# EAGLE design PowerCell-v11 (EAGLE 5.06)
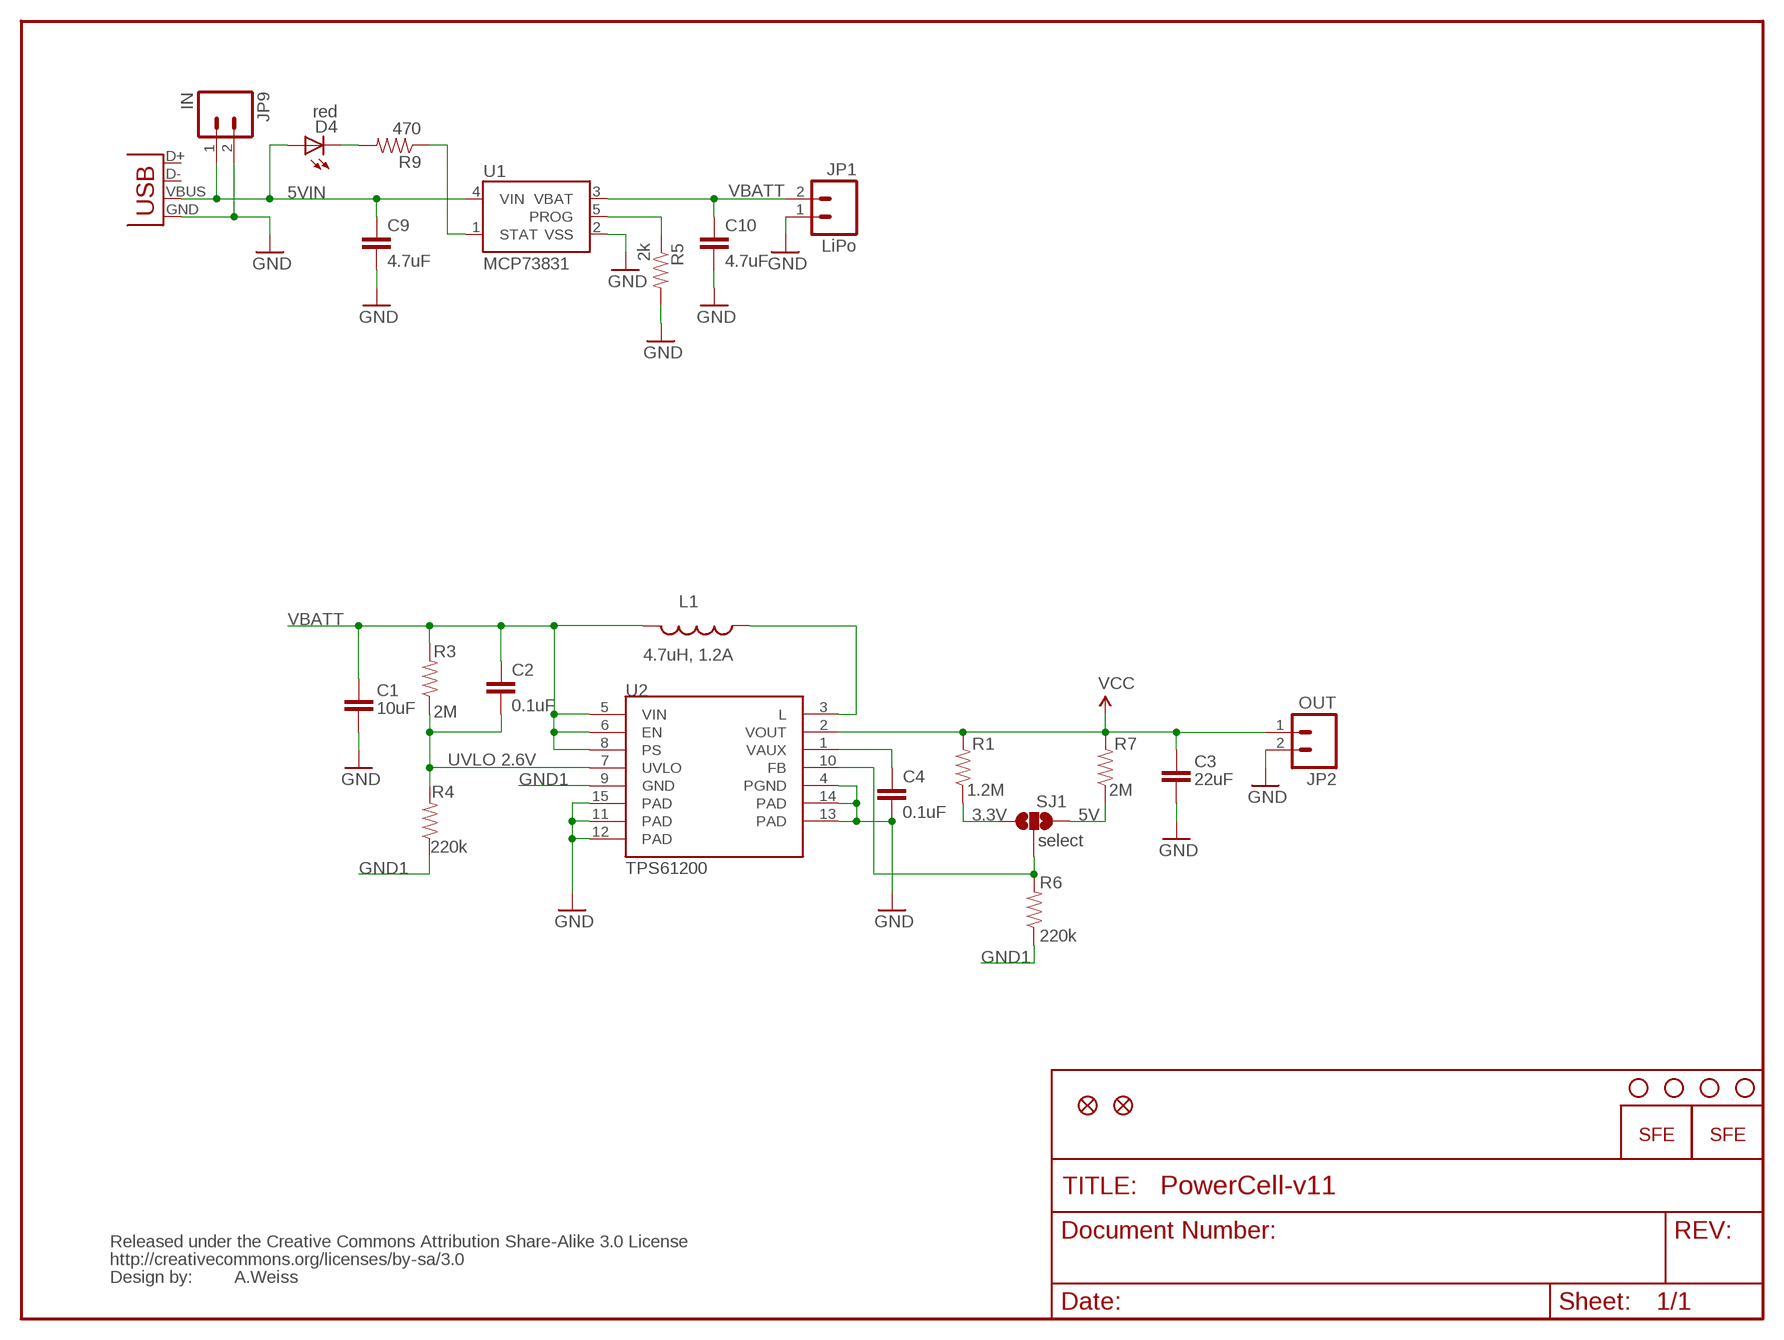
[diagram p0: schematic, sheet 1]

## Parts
C1  10uF  CAP1206  [1206]
C2  0.1uF  CAP0402-CAP  [0402-CAP]
C3  22uF  CAP0805  [0805]
C4  0.1uF  CAP0402-CAP  [0402-CAP]
C9  4.7uF  CAP0402-CAP  [0402-CAP]
C10  4.7uF  CAP0402-CAP  [0402-CAP]
D4  red  LED0603  [LED-0603]
JP1  LiPo  M02-JST-2MM-SMT  [JST-2-SMD]
JP2  OUT  M02PTH  [1X02]
JP3  LOGO-SFENEW  [SFE-NEW-WEBLOGO]
JP4  LOGO-SFESK  [SFE-LOGO-FLAME]
JP5  STAND-OFF  [STAND-OFF]
JP6  STAND-OFF  [STAND-OFF]
JP7  STAND-OFF  [STAND-OFF]
JP8  STAND-OFF  [STAND-OFF]
JP9  IN  M02PTH  [1X02]
JP10  FIDUCIAL1X2  [FIDUCIAL-1X2]
JP11  FIDUCIAL1X2  [FIDUCIAL-1X2]
L1  4.7uH, 1.2A  INDUCTOR.  [CDRH2D09]
R1  1.2M  RESISTOR0402-RES  [0402-RES]
R3  2M  RESISTOR0402-RES  [0402-RES]
R4  220k  RESISTOR0402-RES  [0402-RES]
R5  2k  RESISTOR0402-RES  [0402-RES]
R6  220k  RESISTOR0402-RES  [0402-RES]
R7  2M  RESISTOR0402-RES  [0402-RES]
R9  470  RESISTOR0402-RES  [0402-RES]
SJ1  select  SOLDERJUMPER_2WAYPASTE2&3  [SJ_3_PASTE2&3]
U1  MCP73831  [SOT23-5]
U2  TPS61200  [QFN-10_PAD]
U$1  CREATIVE_COMMONS  [CREATIVE_COMMONS]
X1  USB-MICROB  [USB-MICROB]

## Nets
3.3V: R1.1 SJ1.1
5V: R7.1 SJ1.3
5VIN: C9.1 D4.A JP9.1 U1.4(VIN) X1.VBUS
FB: R6.2 SJ1.2 U2.10(FB)
GND: C1.2 C3.2 C4.2 C9.2 C10.2 JP1.1 JP2.2 JP9.2 R5.2 U1.2(VSS) U2.4(PGND) U2.11(PAD) U2.12(PAD) U2.13(PAD) U2.14(PAD) U2.15(PAD) X1.GND
GND1: R4.1 R6.1 U2.9(GND)
N$1: C4.1 U2.1(VAUX)
N$2: L1.P$1 U2.3(L)
N$8: D4.C R9.2
N$11: R5.1 U1.5(PROG)
N$14: R9.1 U1.1(STAT)
UVLO: C2.2 R3.1 R4.2 U2.7(UVLO)
VBATT: C1.1 C2.1 C10.1 JP1.2 L1.P$2 R3.2 U1.3(VBAT) U2.5(VIN) U2.6(EN) U2.8(PS)
VCC: C3.1 JP2.1 R1.2 R7.2 U2.2(VOUT)
Unconnected: X1.D+ X1.D-

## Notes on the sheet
- UVLO 2.6V
- A.Weiss

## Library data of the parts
C1 C3 = CH_passive:CAP: Capacitor
C2 C4 C9 C10 = SparkFun:CAP: Capacitor
D4 = SparkFun:LED: LEDs
JP1 JP2 JP9 = SparkFun:M02: Header 2
JP3 JP4 = SparkFun:LOGO-SFE: Spark Fun Electronics PCB Logo
JP5-JP8 = SparkFun:STAND-OFF: Stand Off
JP10 JP11 = SparkFun:FIDUCIAL: Fiducial Alignment Points
L1 = SparkFun:INDUCTOR: Inductors
R1 R3-R7 R9 = SparkFun:RESISTOR: Resistor
SJ1 = SparkFun:SOLDERJUMPER_2WAY: Solder Jumper 2 way solder jumper
U1 = SparkFun:MCP73831: Microchip's MCP73831 Miniature single cell, fully integrated Li-Ion, Li-polymer charge management controller http://ww1.microchip.com/downloads/en/DeviceDoc/21984a.pdf
U2 = SparkFun:TPS61200: DC to DC Booster
U$1 = SparkFun:CREATIVE_COMMONS
X1 = SparkFun:USB: USB Connectors USB-B-PTH is fully proven SKU : PRT-00139 USB-miniB is fully proven SKU : PRT-00587 USB-A-PCB is untested. USB-A-H is throughly reviewed, but untested. Spark Fun Electronics SKU : PRT-00437 USB-B-SMT is throughly reviewed, but untested. Needs silkscreen touching up. USB-A-S has not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

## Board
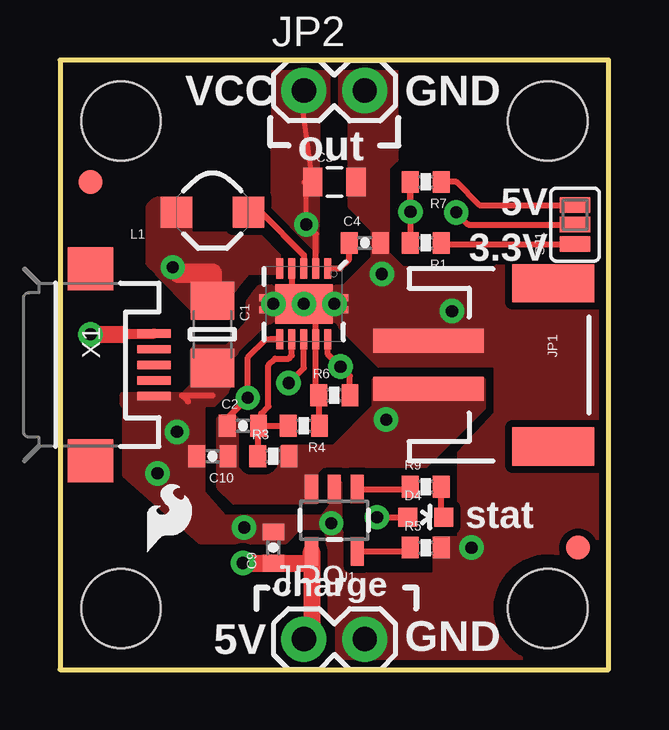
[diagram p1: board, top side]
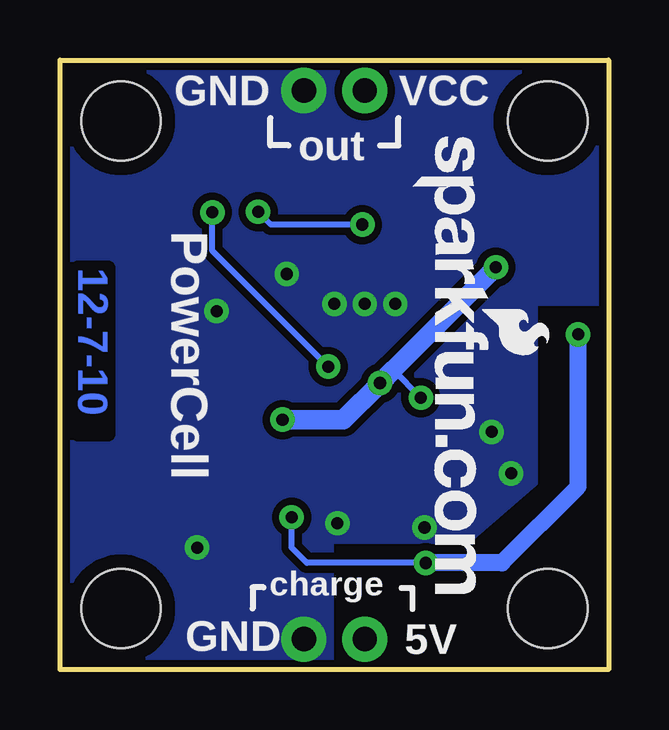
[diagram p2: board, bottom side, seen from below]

Size 22.86 x 25.4 mm. Coordinates in mm from the lower left corner, seen from the top.
Outline: 0,0 22.86,0 22.86,25.4 0,25.4 0,0
Copper layers (1*16): Top 0.035mm / dielectric 1.5mm / Bottom 0.035mm
Design rules "SparkFun": minimum track width 8mil, minimum drill 20mil, track to track 8mil, track to pad 8mil, pad to pad 8mil, via to via 8mil, smd to smd 8mil, copper to edge 8mil, drill to drill 8mil, minimum pad ring 12mil, minimum via ring 10mil, stop-mask expansion 4mil, vias tented up to drill 20mil, thermal gap 10mil

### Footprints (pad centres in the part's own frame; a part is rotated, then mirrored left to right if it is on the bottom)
1206 = smd 1.6 x 1.8: 1 -1.4,0; 2 1.4,0
0402-CAP = smd 0.7 x 0.9: 1 -0.65,0; 2 0.65,0
0805 = smd 0.8 x 1.2: 1 -0.9,0; 2 0.9,0
LED-0603 = smd 0.8 x 0.8: A 0,-0.75; C 0,0.75
JST-2-SMD = smd 1 x 4.6: 1 -1,-3.7; 2 1,-3.7 | smd 1.6 x 3.4: NC1 -3.4,1.5; NC2 3.4,1.5
1X02 = drill 1.016 pad 1.88 round: 1 0,0; 2 2.54,0
STAND-OFF = hole 3.302: 0,0
FIDUCIAL-1X2 = smd 1 x 1: 1 0,0
CDRH2D09 = smd 1.3 x 1.3: P$1 -1.5,0; P$2 1.5,0
0402-RES = smd 0.7 x 0.9: 1 -0.65,0; 2 0.65,0
SJ_3_PASTE2&3 = smd 0.635 x 1.27: 1 -0.813,0; 2 0,0; 3 0.813,0
SOT23-5 = smd 0.55 x 1.2: 1 -0.95,-1.3; 2 0,-1.3; 3 0.95,-1.3; 4 0.95,1.3; 5 -0.95,1.3
QFN-10_PAD = smd 0.297 x 0.85: 1 -1,-1.475; 2 -0.5,-1.475; 3 0,-1.475; 4 0.5,-1.475; 5 1,-1.475; 6 1,1.475; 7 0.5,1.475; 8 0,1.475; 9 -0.5,1.475; 10 -1,1.475 | smd 0.7 x 0.28: 11 -1.5,0.25; 12 -1.5,-0.25; 13 1.5,0.25; 14 1.5,-0.25 | smd 2.4 x 1.65: 15 0,0
USB-MICROB = smd 0.35 x 1.4: D+ 0,2.65; D- -0.65,2.65; GND 1.3,2.65; ID 0.65,2.65; VBUS -1.3,2.65 | smd 1.8 x 1.9: MT1 -4,0; MT2 4,0

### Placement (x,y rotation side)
C1  6.35,13.97 270 top
C2  7.62,10.16 0 top
C3  11.43,20.32 0 top
C4  12.7,17.78 0 top
C9  8.89,5.08 90 top
C10  6.35,8.89 180 top
D4  15.24,6.35 270 top
JP1  19.05,12.7 270 top
JP2  10.16,24.13 0 top
JP3  8.15,22.2 270 bottom
JP4  3.63,4.9 0 top
JP5  2.54,2.54 0 top
JP6  20.32,2.54 0 top
JP7  2.54,22.86 0 top
JP8  20.32,22.86 0 top
JP9  10.16,1.27 0 top
JP10  21.59,5.08 0 top
JP11  1.27,20.32 0 top
L1  6.35,19.05 180 top
R1  15.24,17.78 180 top
R3  8.89,8.89 0 top
R4  10.16,10.16 180 top
R5  15.24,5.08 0 top
R6  11.43,11.43 0 top
R7  15.24,20.32 180 top
R9  15.24,7.62 0 top
SJ1  21.46,18.54 90 top
U1  11.43,6.22 180 top
U2  10.16,15.24 180 top
U$1  not placed on the board
X1  1.27,12.7 270 top

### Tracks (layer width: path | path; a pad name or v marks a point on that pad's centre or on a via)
3.3V
  Top 0.254: SJ1.1 15.94,17.73 R1.1
5V
  Top 0.254: SJ1.3 17.48,19.36 16.51,20.32 R7.1
5VIN  (via drill 0.51)
  Top 0.254: v13.21,6.35 D4.A
  Top 0.406: X1.VBUS 2.57,14 2.54,13.97
  Top 0.61: v7.62,4.45 7.63,4.43 | 10.4,4.43 10.41,4.45 10.41,4.86 U1.4
  Top 0.711: 7.63,4.43 C9.1 10.4,4.43 | U1.4 10.48,1.59 JP9.1 | v1.27,13.97 2.54,13.97
  Bottom 0.254: v13.21,6.35 13.21,5.08 12.57,4.45 v7.62,4.45
  Bottom 0.711: v7.62,4.45 4.45,4.45 1.27,7.62 v1.27,13.97
FB  (via drill 0.51)
  Top 0.254: SJ1.2 17.02,18.54 v16.51,19.05 | U2.10 11.16,13.15 v11.68,12.62 12.08,12.23 R6.2
  Bottom 0.254: v16.51,19.05 16.51,17.45 v11.68,12.62
GND  (via drill 0.51)
  Top 0.254: U2.4 9.66,15.74 U2.15 | 5.33,11.18 5.08,11.43 6.35,11.43
  other vias: 8.89,15.24 11.43,15.24 10.16,15.24 16.33,14.94 13.41,16.48 4.88,9.91 11.3,6.1 7.67,5.92 4.06,8.18 17.14,5.08
  pour Bottom (isolate 0.305, no thermals): 0,25.4 0,15.24 3.05,15.24 3.05,7.75 5.84,5.33 11.56,5.33 11.56,0 22.86,0 22.86,25.4
  pour Top (isolate 0.305, no thermals): 2.62,11.05 2.62,11.46 5.16,11.46 5.54,11.84 5.54,13.31 5.66,13.44 6.96,13.44 7.59,14.07 7.49,14.07 7.87,14.5 7.87,15.32 8.18,15.75 8.23,15.8 8.33,15.93 8.56,15.93 11.89,15.95 13.08,17.14 13.08,18.31 12.12,19.28 12.12,22.91 11.71,23.32 11.71,25.4 13.97,25.4 13.97,21.26 13.61,20.9 13.61,17.32 14.22,16.71 17.58,16.69 18.41,16.74 18.29,12.7 13.31,12.7 11.51,14.5 8.61,14.5 7.14,13.03 7.14,11.81 6.38,11.05
  pour Top (isolate 0.305, no thermals): 2.67,11.05 2.67,8.13 5.84,5.33 9.4,5.33 9.91,5.84 11.05,5.84 11.56,5.33 11.56,0 22.86,0 22.86,16.76 18.16,16.76 18.16,10.67 16.64,9.02 16.64,3.94 11.94,3.94 11.68,4.19 11.68,7.75 11.56,7.87 11.43,7.87 11.3,7.75 11.3,6.86 10.92,6.35 6.86,6.35 5.97,7.37 5.97,11.05
  pour Top (isolate 0.305, no thermals): 16.51,5.46 15.62,5.46 15.62,4.06 16.64,4.06 16.64,5.33
  pour Top (isolate 0.305, no thermals): 10.9,5.87 10.9,5.84 11.15,5.59 11.15,2.39 11.48,2.06 11.58,2.06 11.76,2.24 11.71,5.71 11.58,5.89 11.58,6.2 11.43,6.35 11.38,6.35
GND1
  Top 0.254: 10.67,14.61 10.66,14.6 U2.9 10.66,11.55 R6.1 10.78,10.19 R4.1
N$1
  Top 0.254: U2.1 11.69,16.71 12.05,17.08 C4.1
N$2
  Top 0.254: U2.3 10.16,17.27 8.38,19.05 L1.P$1
N$8
  Top 0.254: R9.2 15.89,6.45 D4.C
N$11
  Top 0.254: U1.5 14.43,4.92 R5.1
N$14
  Top 0.254: U1.1 14.49,7.52 R9.1
UVLO
  Top 0.254: C2.2 R4.2 | U2.7 9.66,13.09 9.53,12.95 8.97,12.95 8.69,12.68 8.69,10.97 8.38,10.67 8.38,10.27 C2.2 | C2.2 8.27,8.92 R3.1
VBATT  (via drill 0.51)
  Top 0.254: v9.53,11.94 10.16,12.57 U2.8 | 8.76,13.77 U2.6 8.59,13.77 7.82,13.01 v7.82,11.33 6.97,10.47 C2.1 6.99,10.16
  Top 0.813: C1.1 6.35,16.51 4.95,16.51 v4.7,16.76
  Top 1.016: 14.88,11.7 JP1.2
  Bottom 0.254: v7.82,11.33 8.98,12.48
  Bottom 0.813: v4.7,16.76 8.98,12.48 v9.53,11.94 11.05,10.41 v13.59,10.41
  pour Top (isolate 0.305, no thermals): 8.2,18.16 9.19,17.14 9.19,16.54 7.8,16.54 7.52,16.18 7.11,15.65 7.14,14.66 5.74,14.66 5.54,14.86 5.54,15.01 4.06,16.48 4.06,16.51 3.68,16.89 3.68,19.3 3.94,19.56 4.06,19.61 5.41,19.61 5.41,18.16
  pour Top (isolate 0.305, no thermals): 13.08,12.06 13.08,10.92 11.43,9.27 9.27,9.27 9.14,9.14 9.14,8.38 8.89,8.13 7.62,8.13 7.37,8.38 7.37,10.41 7.24,10.54 6.73,10.54 6.6,10.41 6.6,7.62 7.24,6.99 10.67,6.99 10.67,8.26 10.92,8.51 15.24,8.51 17.65,10.92 17.65,12.06
VCC  (via drill 0.51)
  Top 0.203: v10.26,18.54 10.26,20.22 10.16,20.32 | C3.1 10.03,24 JP2.1
  Top 0.254: R1.2 R7.2 14.59,19.09 v14.61,19.07 | U2.2 10.66,18.14 v10.26,18.54
  Bottom 0.254: v10.26,18.54 14.07,18.54 v14.61,19.07
  pour Top (isolate 0.305, no thermals): 8.89,25.4 8.86,19.18 10.72,17.27 10.72,17.17 10.77,23.06 11.18,23.47 11.18,25.4

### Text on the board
Bottom: 12-7-10
tPlace: VCC | GND | out | 5V | 3.3V | stat | charge | 5V | GND
bPlace: VCC | GND | out | PowerCell | charge | 5V | GND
